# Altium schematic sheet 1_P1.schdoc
size 423 x 300 mm
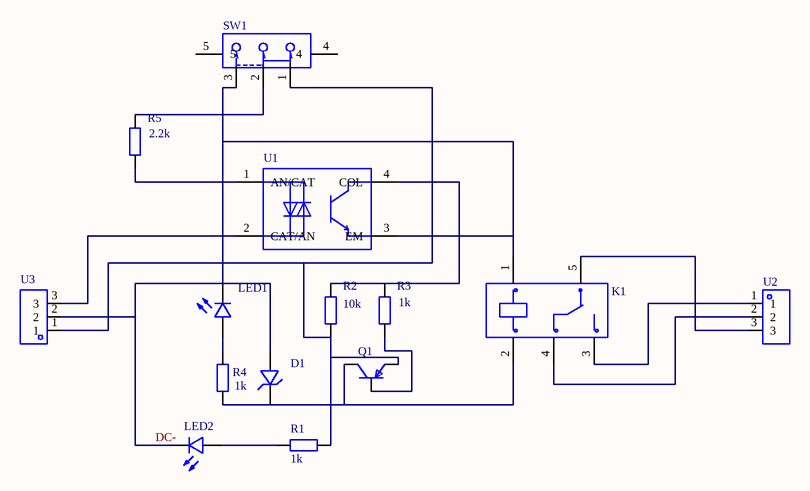
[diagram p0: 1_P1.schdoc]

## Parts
D1  (no value)  [LL-34_L3.5-W1.5-RD]
K1  (no value)  [RELAY-TH_HF3FF-XX-1ZXX-XXX]
LED1  (no value)  [LED0603-R-RD]
LED2  (no value)  [LED0603-R-RD]
Q1  (no value)  [SOT-23-3_L2.9-W1.3-P1.90-LS2.4-BR]
R1  value 1k  [R0603]
R2  value 10k  [R0603]
R3  value 1k  [R0603]
R4  value 1k  [R0603]
R5  value 2.2k  [R0603]
SW1  (no value)  [SW-TH_SK-12D02VG3]
U1  (no value)  [SOP-4_L3.9-W4.4-P2.54-LS7.0-TL]
U2  (no value)  [CONN-TH_3P-P5.00_KF301-5.0-3P]
U3  (no value)  [CONN-TH_3P-P5.00_KF301-5.0-3P]

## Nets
DC-: D1.2(A) K1.1 LED1.2(C) LED2.2(C) SW1.3 U1.3(EM) U3.2
NetD1_1: D1.1(C) K1.2 Q1.3(C) R4.1
NetK1_3: K1.3 U2.1
NetK1_4: K1.4 U2.2
NetK1_5: K1.5 U2.3
NetLED1_1: LED1.1(A) R4.2
NetLED2_1: LED2.1(A) R1.1
NetQ1_1: Q1.1(B) R3.1
NetQ1_2: Q1.2(E) R1.2 R2.1 SW1.1 U3.1
NetR2_2: R2.2 R3.2 U1.4(COL)
NetR5_1: R5.1 U1.1(AN/CAT)
NetR5_2: R5.2 SW1.2
NetU1_2: U1.2(CAT/AN) U3.3

Not connected (* = marked no-connect by the designer): SW1 4 5

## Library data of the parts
D1 = GLZ5.1B_R1_10001: Manufacturer: PANJIT(强茂); Add into BOM: yes; Diode Configuration: 独立式; Zener Voltage (Range): 4.94V~5.2V; Power Dissipation: 500mW; Reverse Leakage Current (Ir): 5A@1.5V; Zener Impedance (Zzt): 20; Description: 二极管配置:独立式;稳压值(标称值):-;稳压值(范围):4.94V~5.2V;精度:-;功率:500mW;反向电流(Ir):5A@1.5V;阻抗(Zzt):20;
K1 = JQC-3FF/005-1ZS(551): Manufacturer: HF(宏发); Symbol: JQC-3FF/05-1ZS(551); Add into BOM: yes; Relay Type: General Purpose; Coil Type: Non Latching; Coil Voltage: 5VDC; Contact Form: SPDT; Contact Rating (Current): 10A; Switching Voltage: (277VAC , 28VDC) Max; Description: 继电器类型:General Purpose;线圈类型:Non Latching;线圈电压:5VDC;触点形式:SPDT;触点的额定电流:10A;
LED1 LED2 = 19-217/GHC-YR1S2/3T: Manufacturer: EVERLIGHT(台湾亿光); Add into BOM: yes; Emitted Color: 翠绿; Lens Color: 无色透明; Dominant Wavelength: 520nm~535nm; Peak Wavelength: 518nm; Forward Current: 20mA; Forward Voltage (VF): 3.3V; Luminous Intensity: 285mcd; Power Dissipation: 110mW; Viewing Angle: 120°; Description: 发光颜色:翠绿;二极管配置:-;透镜颜色:无色透明;主波长:520nm~535nm;峰值波长:518nm;色温:-;光通量(25时):-;测试电流:20mA;正向电压(VF):3.3V;发光强度:285mcd;功率:110mW;发光角度:120°;安装方式:-;工作温度:-40~+85;
Q1 = S8550 2TY: Manufacturer: CJ（江苏长电/长晶）; Symbol: S8550_C2147; Add into BOM: yes; Transistor Type: PNP; Collector-Emitter Breakdown Voltage (Vceo): 25V; Collector Current (Ic): 500mA; Power Dissipation (Pd): 300mW; Description: 晶体管类型:PNP;集射极击穿电压(Vceo):25V;集电极电流(Ic):500mA;功率(Pd):300mW;; NAME: E; NUMBER: 2
R1-R5 = TR0603B10K0P0525Z: Manufacturer: EVER OHMS(天二科技); Symbol: TR0603B10KP05250.1W; Add into BOM: yes; Tolerance: ±0.1%; Power(Watts): 100mW; Temperature Coefficient: ±25ppm/; Overload Voltage (Max): 75V; Description: 电阻类型:薄膜电阻;阻值:10k;精度:±0.1%;功率:100mW;温度系数:±25ppm/;最大工作电压:75V;工作温度范围:-55~+155;
SW1 = SK-12D02VG3: Manufacturer: SOFNG(硕方); Add into BOM: yes; Current Rating (DC): 200mA; Voltage Rating (DC): 30V; Circuit: 单刀双掷; Mechanical Life: 8000; Actuator Style: 矩形柱状; Pin Style: PC引脚; Description: 额定电流(DC):200mA;额定电压(DC):30V;额定电流(AC):-;额定电压(AC):-;电路结构:单刀双掷;安装方式:卧插;机械寿命:8000;滑钮形状:矩形柱状;引脚样式:PC引脚;工作温度:-10~+60;开关高度:-;
U1 = LTV-354T-A: Manufacturer: LITEON(台湾光宝); Add into BOM: yes; Input Type: AC, DC; Number of Channels: 1; Voltage-Isolation: 3750Vrms; Output-Voltage(Max): 35V; Output-Current(Max): 50mA; Description: 产品类型:晶体管输出;输入类型:AC, DC;通道数目:1;隔离电压:3750Vrms;
U2 U3 = KF301-5.0-3P: Manufacturer: KEFA(科发); Add into BOM: yes; Pitch: 5mm; Number of PINs Per Row: 3; Current Rating (Max): 17A; Voltage Rating (Max): 250V; Wire Gauge - AWG: 14~22; Wire Gauge - mm?: 1.5; Description: 间距:5mm;排数:1;每排PIN数:3;安装方式:直针;额定电流:17A;额定电压:250V;线规 - AWG:14~22;线规 - mm?:1.5;工作温度范围:-30~+120;颜色:蓝色;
